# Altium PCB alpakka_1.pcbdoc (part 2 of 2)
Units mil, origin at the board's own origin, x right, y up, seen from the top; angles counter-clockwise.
Board outline 6704.54 x 4318.9 mil, 4 copper layers (Top Layer, Inner1, Inner2, Bottom Layer); 97 components, 87 nets, 400 pads, 319 vias.
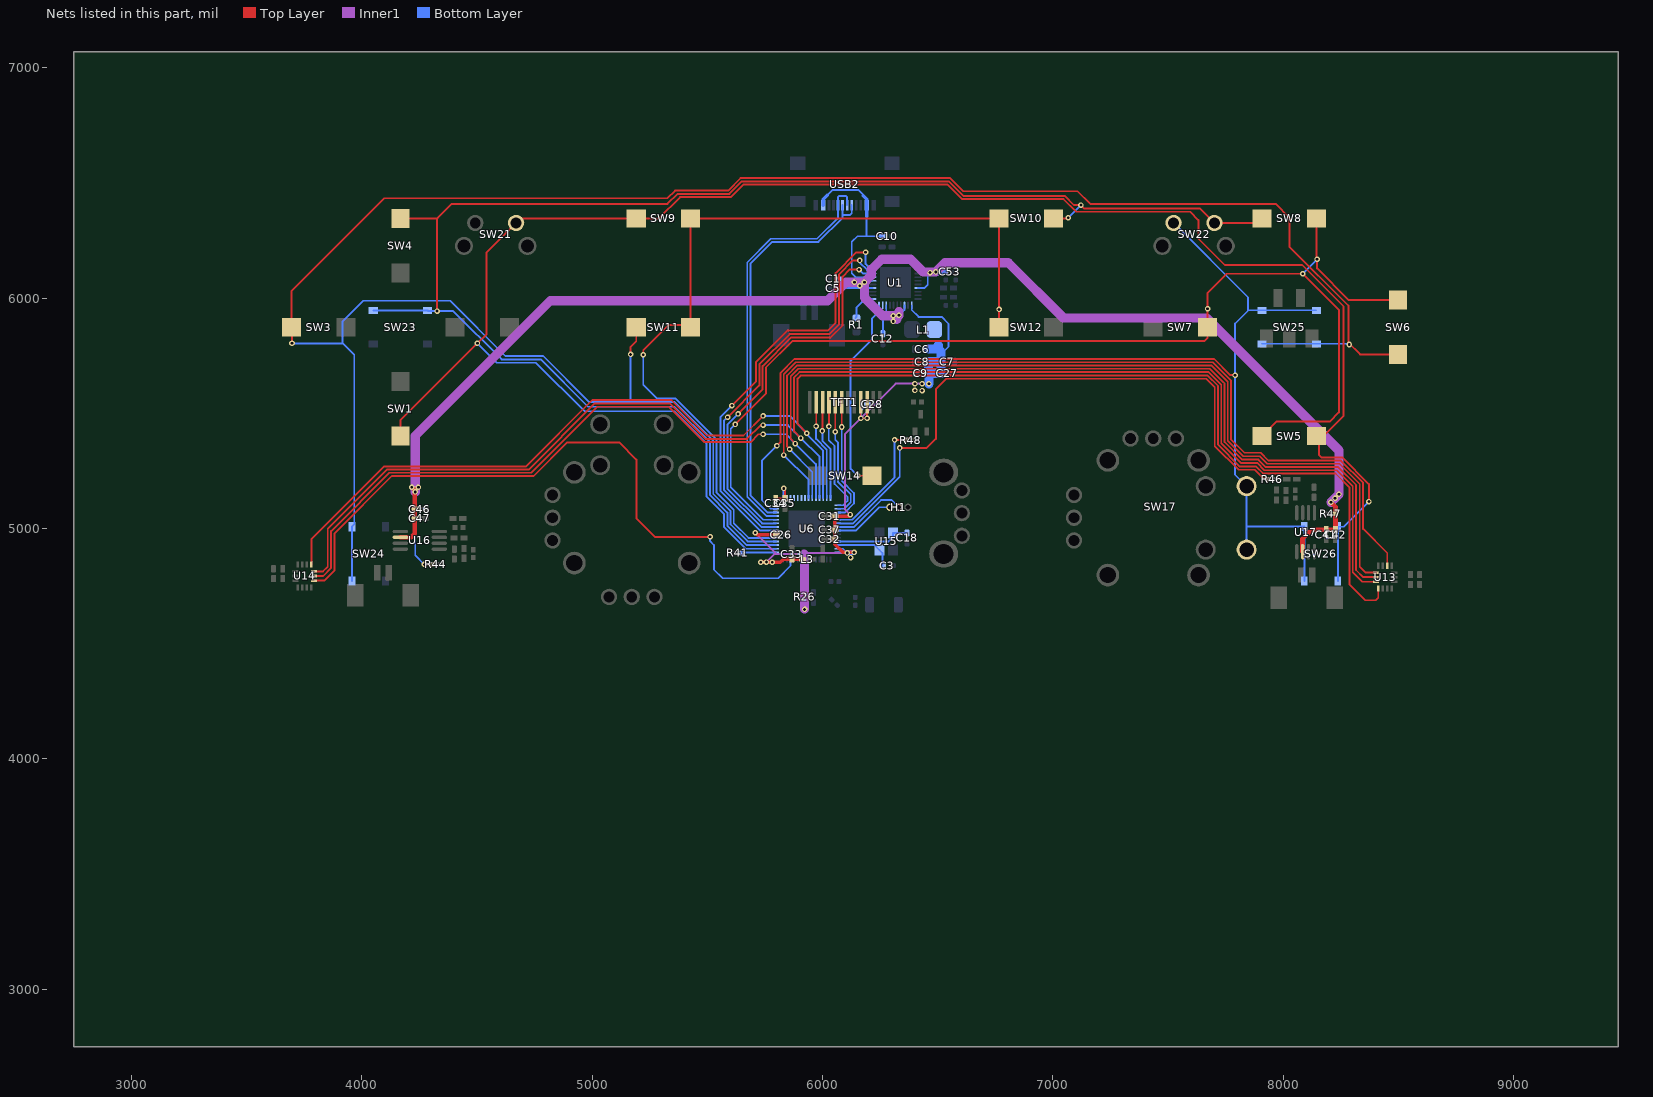
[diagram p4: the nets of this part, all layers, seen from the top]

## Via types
v1: diameter 24.02, hole 12.01, Top Layer to Bottom Layer, 310 vias
v2: diameter 24, hole 12, Top Layer to Bottom Layer, 9 vias

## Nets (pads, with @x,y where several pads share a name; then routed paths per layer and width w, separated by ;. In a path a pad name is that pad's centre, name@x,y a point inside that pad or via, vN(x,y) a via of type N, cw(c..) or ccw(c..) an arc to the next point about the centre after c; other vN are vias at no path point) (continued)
GPIO7: U6.12 U14.12 | length 2927.4
  Top Layer w8: U14.12@3792.13,4773.54 3837.58,4773.54 3882.27,4818.23 3882.27,4978.23 4131.27,5227.23 4746.27,5227.23 4892.27,5373.23 5117.27,5373.23 5192.27,5298.23 5192.27,5043.23 5272.27,4963.23 v1(5512.27,4963.23)
  Bottom Layer w8: v1(5512.27,4963.23) 5512.27,4944.35 5529.28,4927.34 5529.28,4821.22 5567.17,4783.33 5807.37,4783.33 5861.4,4837.36 U6.12@5861.4,4864.07
GPIO10: R41.2 U6.15 | length 149.8
  Bottom Layer w8: R41.2@5649.31,4898.23 5651.66,4895.87 U6.15@5798.11,4895.87
GPIO11: SW1.1 SW5.1 SW9.1 SW21.1 SW26.3 SW26.4 U6.16 | length 8373.5
  Top Layer w8: SW1.1@4168.16,5400.65 4168.16,5469.12 v1(4502.27,5803.23) 4542.27,5843.23 4542.27,6198 SW21.1@4670.12,6325.86 4689.82,6345.56 SW9.1@5191.75,6345.56 5289.6,6345.56 5382.27,6438.23 5602.27,6438.23 5656.27,6492.23 6543.07,6492.23 6606.18,6429.11 7046.39,6429.11 7101.27,6374.23 7596.27,6374.23 7632.27,6338.23 7632.27,6258.23 7747.27,6143.23 8082.27,6143.23 8262.27,5963.23 8262.27,5488.23 SW5.1@8156.27,5382.23 ; SW5.1@8144.47,5400.66 8144.47,5394.03 SW5.1@8156.27,5382.23 ; v1(8372.27,5116.24) 8372.27,5192.22 8256.26,5308.23 8165.28,5308.23 8156.27,5317.23 SW5.1@8156.27,5382.23
  Bottom Layer w8: v1(4502.27,5803.23) 4586.26,5719.24 4756.26,5719.24 4967.27,5508.23 5357.87,5508.23 5496.27,5369.83 5496.27,5139.23 5572.27,5063.23 5572.27,5006.18 5666.83,4911.61 U6.16@5798.11,4911.61 ; SW21.1@4670.12,6325.86 SW21.1@4675.12,6320.86 ; SW26.4@8238.09,4770.95 8238.09,5007.17 8263.2,5007.17 v1(8372.27,5116.24)
GPIO12: SW4.1 SW8.1 SW10.1 SW22.1 SW23.3 SW23.4 U6.17 | length 6789.4
  Top Layer w8: SW4.1@4168.16,6345.47 4328.24,6345.47 ; v1(4327.27,5943.23) 4327.27,6344.5 4328.24,6345.47 ; SW10.1@7002.77,6345.56 7064.6,6345.56 v1(7067.27,6348.23) ; SW8.1@7908.25,6360.91 SW8.1@7908.25,6345.56 7888.55,6325.86 SW22.1@7701.62,6325.86 7639.25,6388.23 7137.27,6388.23 v1(7122.27,6403.23) 7092.07,6403.23 7052.18,6443.11 6611.98,6443.11 6548.87,6506.23 5650.07,6506.23 5596.07,6452.23 5371.27,6452.23 5327.27,6408.23 4391,6408.23 4328.24,6345.47
  Bottom Layer w8: SW23.3@4050.05,5945.89 SW23.4@4286.27,5945.89 4288.93,5943.23 v1(4327.27,5943.23) 4397.27,5943.23 4607.27,5733.23 4777.27,5733.23 4982.27,5528.23 5357.67,5528.23 5512.27,5373.63 5512.27,5143.43 5587.27,5068.43 5587.27,5010.97 5670.88,4927.36 U6.17@5798.11,4927.36 ; v1(7067.27,6348.23) v1(7122.27,6403.23)
GPIO13: SW3.1 SW6.1 SW11.1 SW24.1 SW24.2 SW25.3 SW25.4 U6.18 | length 10327.3
  Top Layer w8: v1(3697.27,5803.23) 3697.27,5871.44 SW3.1@3695.65,5873.06 3695.65,6031.61 4097.27,6433.23 5327.27,6433.23 5360.27,6466.23 5590.27,6466.23 5644.27,6520.23 6554.67,6520.23 6611.67,6463.23 7107.27,6463.23 7162.27,6408.23 7967.27,6408.23 8027.27,6348.23 8027.27,6223.23 8283.75,5966.75 8283.75,5805.06 8333.86,5754.95 SW6.1@8498.86,5754.95 ; v1(5167.27,5755.24) 5167.27,5788.23 5191.75,5812.71 SW11.1@5191.75,5873.06
  Bottom Layer w8: v1(3697.27,5803.23) 3917.27,5803.23 ; SW24.2@3957.53,4770.75 SW24.1@3957.53,5006.97 3967.53,5016.97 3967.53,5752.97 3917.27,5803.23 ; v1(5167.27,5755.24) 5167.27,5549.5 5167.76,5549.01 ; U6.18@5798.11,4943.11 5674.93,4943.11 5601.27,5016.77 5601.27,5074.23 5526.27,5149.23 5526.27,5379.43 5356.68,5549.01 5167.76,5549.01 ; SW25.4@7907.15,5801.23 8143.37,5801.23 8284.27,5801.23 v1(8287.27,5798.23) ; 3917.27,5803.23 3917.27,5898.23 4007.27,5988.23 4383.4,5988.23 4623.4,5748.23 4787.27,5748.23 4986.48,5549.01 5167.76,5549.01
GPIO14: SW9.2 SW10.2 SW11.2 SW12.2 U6.19 | length 3708.5
  Top Layer w8: v1(5222.27,5753.23) 5222.27,5773.23 5332.1,5883.06 5417.97,5883.06 SW11.2@5427.97,5873.06 SW9.2@5427.97,6345.56 SW10.2@6766.55,6345.56 v1(6766.55,5950.4) SW12.2@6766.55,5873.06
  Bottom Layer w8: v1(5222.27,5753.23) 5222.27,5623.23 5282.27,5563.23 5362.27,5563.23 5540.27,5385.23 5540.27,5155.23 5615.27,5080.23 5615.27,5022.57 5678.98,4958.86 U6.19@5798.11,4958.86
GPIO15: U1.40 U6.21 | length 1819.7
  Top Layer w8: v1(5607.27,5533.23) 5712.27,5638.23 5712.27,5723.23 5847.27,5858.23 6022.27,5858.23 6057.27,5893.23 6057.27,6108.23 6147.27,6198.23 v1(6187.27,6198.23)
  Bottom Layer w8: v1(5607.27,5533.23) 5595.72,5521.68 5595.72,5521.25 5557.27,5482.8 5557.27,5163.23 5730.14,4990.35 U6.21@5798.11,4990.35 ; v1(6187.27,6198.23) 6187.27,6148.03 6197.61,6137.69 U1.40@6218.17,6137.69
GPIO16: U1.39 U6.22 | length 1729.8
  Top Layer w8: v1(5588.28,5482.68) 5726.27,5620.67 5726.27,5712.23 5857.27,5843.23 6029.49,5843.23 6072.27,5886.01 6072.27,6103.23 6132.27,6163.23 v1(6162.27,6163.23)
  Bottom Layer w8: v1(5588.28,5482.68) 5572.27,5466.67 5572.27,5168.03 5734.19,5006.1 U6.22@5798.11,5006.1 ; v1(6162.27,6163.23) 6162.27,6153.23 6193.61,6121.89 U1.39@6218.17,6121.89
GPIO17: U1.38 U6.23 | length 1651.2
  Top Layer w8: v1(5633.61,5496.89) 5740.27,5603.55 5740.27,5704.22 5865.28,5829.23 6035.84,5829.23 6087.27,5880.65 6087.27,6093.23 6117.27,6123.23 v1(6159.28,6123.23)
  Bottom Layer w8: v1(5633.61,5496.89) 5587.27,5450.55 5587.27,5172.83 5738.24,5021.85 U6.23@5798.11,5021.85 ; v1(6159.28,6123.23) 6176.32,6106.19 U1.38@6218.17,6106.19
GPIO18: SW5.2 SW6.2 SW7.2 SW8.2 U6.24 | length 5210.5
  Top Layer w8: v1(5621.33,5451.17) 5754.27,5584.1 5754.27,5698.42 5869.08,5813.23 7657.27,5813.23 7672.07,5828.03 SW7.2@7672.07,5873.06 v1(7672.07,5953.23) 7672.07,6023.03 7754.55,6105.51 v1(8084.99,6105.51) 8242.27,5948.23 8242.27,5503.23 8202.27,5463.23 7970.82,5463.23 SW5.2@7908.25,5400.66 ; SW8.2@8144.47,6345.56 8144.47,6171.03 v1(8147.27,6168.23) 8147.27,6128.23 8284.33,5991.17 SW6.2@8498.86,5991.17
  Bottom Layer w8: v1(5621.33,5451.17) 5602.27,5432.1 5602.27,5177.63 5742.29,5037.6 U6.24@5798.11,5037.6 ; v1(8084.99,6105.51) 8147.27,6167.79 v1(8147.27,6168.23)
GPIO19: U6.25 USB2.A7 USB2.B7 | length 1820.4
  Bottom Layer w8: U6.25@5798.11,5053.35 5777.02,5053.35 5776.15,5054.22 5756.27,5054.22 5673.27,5137.23 5673.27,6154.23 5776.37,6257.33 5976.37,6257.33 6067.73,6348.69 USB2.B7@6067.73,6403.19 6067.27,6403.65 6067.27,6438.23 6072.27,6443.23 6102.27,6443.23 6107.1,6438.39 USB2.A7@6107.1,6403.19
GPIO20: U6.26 USB2.A6 USB2.B6 | length 1763.6
  Bottom Layer w8: U6.26@5798.11,5069.09 5777.02,5069.09 5776.15,5068.22 5762.27,5068.22 5687.27,5143.23 5687.27,6148.43 5782.17,6243.33 5982.17,6243.33 6087.42,6348.58 6087.42,6359.84 ; USB2.A6@6087.42,6403.19 6087.42,6359.84 ; USB2.B6@6126.79,6403.19 6127.27,6402.71 6127.27,6368.23 6118.88,6359.84 6087.42,6359.84
GPIO21: SW17.b SW17.d SW22.2 SW25.1 SW25.2 SW26.1 SW26.2 U6.27 | length 5069.6
  Top Layer w8: v1(5802.27,5358.23) 5817.27,5373.23 5817.27,5674.23 5878.26,5735.23 7700.27,5735.23 7770.42,5665.08 v1(7791.01,5665.08)
  Bottom Layer w8: U6.27@5798.11,5084.84 5775.65,5084.84 5737.27,5123.23 5737.27,5293.23 v1(5802.27,5358.23) ; SW22.2@7524.46,6325.86 7847.27,6003.05 7847.27,5945.41 ; SW17.b@7841.01,4907.77 7841.01,5008.23 ; SW26.2@8092.43,4770.95 8092.43,5007.17 8091.37,5008.23 7841.01,5008.23 ; SW25.1@8143.37,5946.89 7848.74,5946.89 7847.27,5945.41 ; 7841.01,5008.23 SW17.d@7841.01,5183.36 7791.01,5233.36 v1(7791.01,5665.08) 7791.01,5889.15 7847.27,5945.41
GPIO33: U6.38 U13.13 U14.13 | length 6450.1
  Top Layer w8: U14.13@3792.13,4793.23 3832.27,4793.23 3867.27,4828.23 3867.27,4988.23 4120.27,5241.23 4735.27,5241.23 5022.27,5528.23 5332.27,5528.23 5486.27,5374.23 5688.27,5374.23 5722.27,5408.23 v1(5742.27,5408.23) ; v1(5882.27,5368.23) 5862.27,5388.23 5862.27,5659.84 5895.66,5693.23 7682.27,5693.23 7740.27,5635.23 7740.27,5635.03 7745.27,5630.03 7745.27,5375.43 7822.47,5298.23 7892.67,5298.23 7924.67,5266.23 8238.87,5266.23 8316.27,5188.83 8316.27,4819.23 8347.27,4788.22 U13.13@8402.41,4788.22
  Bottom Layer w8: v1(5742.27,5408.23) 5842.27,5408.23 v1(5882.27,5368.23) 5971.64,5278.85 U6.38@5971.64,5132.38
GPIO34: U6.39 U13.14 U14.14 | length 6472.4
  Top Layer w8: U14.14@3792.13,4812.91 3831.95,4812.91 3852.27,4833.23 3852.27,4998.23 4109.27,5255.23 4724.27,5255.23 5011.27,5542.23 5338.07,5542.23 5492.07,5388.23 5672.27,5388.23 5732.27,5448.23 v1(5742.27,5448.23) ; v1(5906.05,5392) 5877.27,5420.78 5877.27,5655.04 5900.46,5678.23 7677.27,5678.23 7731.27,5624.23 7731.27,5369.03 7816.07,5284.23 7886.87,5284.23 7918.87,5252.23 8233.07,5252.23 8302.27,5183.03 8302.27,4809.99 8343.71,4768.54 U13.14@8402.41,4768.54
  Bottom Layer w8: v1(5742.27,5448.23) 5849.82,5448.23 v1(5906.05,5392) 5987.39,5310.66 U6.39@5987.39,5132.38
GPIO35: U6.40 U13.1 U14.1 | length 6573.7
  Top Layer w8: U14.1@3781.8,4842.91 3781.8,4952.76 4098.27,5269.23 4713.27,5269.23 5001.27,5557.23 5344.28,5557.23 5498.28,5403.23 5657.27,5403.23 v1(5742.27,5488.23) ; v1(5932.27,5413.23) 5892.27,5453.23 5892.27,5650.24 5905.26,5663.23 7672.07,5663.23 7717.27,5618.03 7717.27,5363.23 7812.27,5268.23 7883.07,5268.23 7913.07,5238.23 8227.27,5238.23 8287.27,5178.23 8287.27,4758.23 8357.27,4688.23 8402.27,4688.23 8412.74,4698.7 U13.1@8412.74,4738.54
  Bottom Layer w8: v1(5742.27,5488.23) 5857.27,5488.23 v1(5932.27,5413.23) 5932.27,5408.43 6003.13,5337.56 U6.40@6003.13,5132.38
GPIO36: TFT1.11 U6.41 | length 434.2
  Top Layer w8: v1(5972.27,5443.23) 5973.25,5444.21 TFT1.11@5973.25,5546.87
  Bottom Layer w8: v1(5972.27,5443.23) 5972.27,5388.23 6018.88,5341.61 U6.41@6018.88,5132.38
GPIO37: TFT1.10 U6.42 | length 429.5
  Top Layer w8: v1(5999.63,5423.23) 6000.81,5424.41 TFT1.10@6000.81,5546.87
  Bottom Layer w8: v1(5999.63,5423.23) 5999.63,5380.66 6034.63,5345.66 U6.42@6034.63,5132.38
GPIO38: TFT1.9 U6.43 | length 512
  Top Layer w8: v1(6028.37,5442.73) TFT1.9@6028.37,5546.87
  Bottom Layer w8: v1(6028.37,5442.73) 6027.27,5441.62 6027.27,5383.23 6052.27,5358.23 6052.27,5193.23 6108.88,5136.62 6108.88,5119.44 6090.04,5100.59 U6.43@6066.42,5100.59
GPIO39: TFT1.8 U6.44 | length 529.3
  Top Layer w8: v1(6055.93,5419.57) TFT1.8@6055.93,5546.87
  Bottom Layer w8: v1(6055.93,5419.57) 6055.93,5384.57 6067.27,5373.23 6067.27,5203.23 6122.88,5147.62 6122.88,5113.64 6094.09,5084.84 U6.44@6066.42,5084.84
GPIO40: TFT1.7 U6.45 | length 547.7
  Top Layer w8: v1(6083.49,5440.05) TFT1.7@6083.49,5546.87
  Bottom Layer w8: U6.45@6066.42,5069.09 6098.13,5069.09 6136.88,5107.84 6136.88,5153.62 6083.49,5207.01 v1(6083.49,5440.05)
GPIO41: R48.1 U6.47 | length 547.9
  Top Layer w8: v1(6313.29,5384.01) 6357.41,5384.01 6365.23,5376.19 R48.1@6365.23,5383.23
  Bottom Layer w8: U6.47@6066.42,5037.6 6129.6,5037.6 6313.29,5221.3 v1(6313.29,5384.01)
GPIO42: R46.1 U6.48 | length 2658
  Top Layer w8: v1(6335.3,5349.08) 6453.12,5349.08 6492.27,5388.23 6492.27,5603.23 6538.27,5649.23 7666.27,5649.23 7703.27,5612.23 7703.27,5357.43 7806.47,5254.23 7877.27,5254.23 7913.27,5218.23 7930.23,5218.23 R46.1@7935.23,5213.23
  Bottom Layer w8: U6.48@6066.42,5021.85 6133.65,5021.85 6335.3,5223.5 v1(6335.3,5349.08)
GPIO43: H1.2 U6.49 | length 327.3
  Bottom Layer w8: U6.49@6066.42,5006.1 6137.7,5006.1 6254.82,5123.23 6300.52,5123.23 H1.2@6332.09,5091.65
GPIO44: H1.1 U6.50 | length 268.3
  Bottom Layer w8: U6.50@6066.42,4990.35 6144.39,4990.35 6245.7,5091.66 H1.1@6292.72,5091.65
GPIO47: U6.37 U13.12 | length 3883.3
  Top Layer w8: v1(5857.27,5343.23) 5846.27,5354.23 5846.27,5663.64 5889.86,5707.23 7688.27,5707.23 7759.27,5636.23 7759.27,5381.23 7827.27,5313.23 7897.47,5313.23 7930.47,5280.23 8244.67,5280.23 8332.27,5192.63 8332.27,4833.23 8357.58,4807.91 U13.12@8402.41,4807.91
  Bottom Layer w8: v1(5857.27,5343.23) 5955.89,5244.6 U6.37@5955.89,5132.38
GPIO48: U6.36 U13.9 | length 3887.5
  Top Layer w8: v1(5832.27,5318.23) 5832.27,5669.43 5884.06,5721.23 7694.27,5721.23 7773.27,5642.23 7773.27,5387.23 7832.27,5328.23 7902.27,5328.23 7936.27,5294.23 8250.47,5294.23 8347.27,5197.42 8347.27,4997.91 8452.11,4893.07 U13.9@8452.11,4837.91
  Bottom Layer w8: v1(5832.27,5318.23) 5940.14,5210.35 U6.36@5940.14,5132.38
PMIC_PWROK: U1.29
PMIC_PWRON: SW14.2 U1.30 | length 866.8
  Top Layer w8: v1(6152.27,5228.23) SW14.2@6215.38,5228.23
  Bottom Layer w8: v1(6152.27,5228.23) 6122.27,5258.23 6122.27,5728.23 6215.67,5821.63 6215.67,5911.63 6245.67,5941.63 U1.30@6245.67,5968.39
SPICLK: U6.33
SPICS0: U6.32
SPID: U6.35
SPIHD: U6.30
SPIQ: U6.34
SPIWP: U6.31
TS: R1.1 U1.31 | length 133.9
  Bottom Layer w8: R1.1@6142.27,5912.89 6147.27,5917.89 6147.27,5958.23 6184.93,5995.89 U1.31@6218.17,5995.89
VBUS: C10.2 U1.37 USB2.A4 USB2.A9 | length 786.6
  Bottom Layer w8: 6020.94,6446.9 6042.27,6468.23 6157.27,6468.23 6179.77,6445.73 ; 6191.75,6354.23 6191.75,6268.74 6192.27,6268.23 ; U1.37@6218.17,6090.39 6145.11,6090.39 6127.27,6108.23 6127.27,6243.23 6152.27,6268.23 6192.27,6268.23 ; C10.2@6260.81,6268.23 6192.27,6268.23
  Bottom Layer w15: USB2.A4@6002.78,6403.18 6002.78,6428.74 6020.94,6446.9 ; 6177.27,6443.23 6191.75,6428.74 USB2.A9@6191.75,6403.18 6191.75,6354.23
VDD3V3: C6.2 C7.2 C8.2 C9.2 C26.2 C27.2 C28.2 C31.2 C32.2 C33.2 C37.2 L1.2 L3.1 R26.2 TFT1.3 TFT1.4 U1.21 U6.20 U6.46 U6.55 U6.56 | length 3298.8
  Top Layer w8: TFT1.4@6166.17,5546.87 6166.17,5479.33 v1(6167.27,5478.23) v1(6193.73,5478.23) TFT1.3@6193.73,5546.87
  Top Layer w15: v1(5708.54,4980.83) 5716.15,4973.23 C26.2@5800.81,4973.23 ; v1(5732.27,4853.23) v1(5782.1,4853.23) 5817.27,4853.23 5830.81,4866.77 C33.2@5867.27,4866.77 5868.34,4865.7 L3.1@5913.21,4865.7 ; v1(6120.48,5059.61) 6114.1,5053.23 C31.2@6053.73,5053.23 C37.2@6053.73,4993.23 C32.2@6053.73,4953.23 6053.73,4931.77 6090.14,4895.36 v1(6137.27,4895.36)
  Inner1 w8: v1(5708.54,4980.83) 5797.27,4892.1 5797.27,4888.23 ; v1(5756.7,4853.8) 5791.14,4888.23 5797.27,4888.23 ; 5919.81,4888.23 5797.27,4888.23 ; 5929.73,4893.23 v1(6107.27,4893.23) ; v1(6120.48,5059.61) 6097.27,5082.83 6097.27,5408.23 v1(6167.27,5478.23) 6317.27,5628.23 v1(6401.24,5628.23) v1(6432.27,5628.23)
  Inner1 w40: 5919.81,4888.23 5922.27,4885.77 v1@5922.27,4650.03
  Bottom Layer w8: v1(5708.54,4980.83) 5714.76,4974.61 U6.20@5798.11,4974.61 ; v1(5922.27,4648.23) R26.2@5922.27,4686.19 ; U6.56@6066.42,4895.87 6104.62,4895.87 6088.88,4911.61 U6.55@6066.42,4911.61 ; U6.46@6066.42,5053.35 6114.23,5053.35 v1(6120.48,5059.61) ; v1(6167.27,5478.23) 6167.27,5509.69 C28.2@6195.81,5538.23 ; U1.21@6387.47,5968.39 6387.47,5948.03 6417.27,5918.23 6517.27,5918.23 6547.27,5888.23 6547.27,5788.23 6514.71,5755.67
  Bottom Layer w20: v1(6107.27,4893.23) 6109.4,4895.36 v1(6137.27,4895.36)
  Bottom Layer w40: 6459.83,5684.33 C8.2@6459.83,5723.23 C7.2@6514.71,5723.23 ; C6.2@6459.83,5778.23 6487.27,5778.23 6502.27,5793.23 6502.27,5778.23 6514.71,5765.79 6514.71,5755.67 C7.2@6514.71,5723.23 ; v1(6462.27,5628.23) 6462.27,5659.69 ; 6482.27,5673.23 C27.2@6520.81,5673.23 ; C27.2@6514.71,5679.33 C7.2@6514.71,5723.23
  other v1: 6122.27,4873.23 6432.27,5598.23 6401.24,5598.76
VDD_SPI: C34.2 C35.2 U6.29 | length 127.4
  Top Layer w8: C34.2@5797.27,5129.69 C35.2@5837.27,5129.69 5837.27,5168.23 v1(5832.27,5173.23)
  Bottom Layer w8: U6.29@5829.91,5132.38 5829.91,5170.87 v1(5832.27,5173.23)
VRTC: C12.2 U1.28 | length 130
  Bottom Layer w8: C12.2@6262.27,5844.69 6262.27,5923.23 6277.27,5938.23 6277.27,5968.29 U1.28@6277.17,5968.39
VSYS: C1.2 C5.2 C41.2 C42.2 C46.2 C47.2 C53.2 R44.1 R47.1 U1.17 U1.23 U1.34 U1.36 U16.6 U17.6 | length 6991.4
  Top Layer w8: v1(4272.27,4843.23) R44.1@4305.23,4843.23 ; R47.1@8224.31,5063.23 R47.1@8227.27,5060.27
  Top Layer w20: U16.6@4167.78,4961.03 4215.07,4961.03 4230.81,4976.77 C47.2@4230.81,5043.23 C46.2@4230.81,5083.23 4230.81,5156.77 v1(4232.27,5158.23) v1@4232.27,5163.23 ; v1(4217.27,5178.23) v1@4232.27,5163.23 ; v1(4246.09,5178.23) 4232.27,5164.41 v1@4232.27,5163.23 ; U17.6@8084.06,4898.74 8084.06,4955.02 8123.73,4994.69 C41.2@8187.27,4994.69 C42.2@8227.27,4994.69 8227.27,5060.27 8227.27,5093.23 v1(8207.27,5113.23)
  Inner1 w40: v1(4232.27,5158.23) 4232.27,5401.46 4819.04,5988.23 6022.27,5988.23 6102.27,6068.23 v1(6182.27,6068.23) ; 6332.27,5941.66 v1(6332.27,5924.63) 6322.27,5914.63 6322.27,5907.92 v1(6306.96,5923.23) 6260.7,5923.23 6182.27,6001.66 v1(6182.27,6068.23) ; v1(8207.27,5113.23) v1(8225.19,5131.15) v1(8242.27,5148.23) 8242.27,5338.23 7667.22,5913.28 7046.17,5913.28 6806.22,6153.23 6532.27,6153.23 v1(6492.27,6113.23) 6437.27,6113.23 6382.27,6168.23 6257.27,6168.23 6212.27,6123.23 6212.27,6098.23 v1(6182.27,6068.23)
  Bottom Layer w8: v1(4232.27,5158.23) 4232.27,4883.23 v1(4272.27,4843.23) ; C5.2@6068.73,6043.23 C5.2@6071.69,6043.19 ; C1.2@6068.73,6083.23 6068.73,6046.15 C5.2@6071.69,6043.19 ; U1.34@6218.17,6043.19 6217.95,6042.96 6142.54,6042.96 6142.31,6043.19 ; U1.36@6218.17,6074.69 6145.29,6074.69 v1(6138.98,6068.38) 6142.31,6065.05 6142.31,6043.19 ; v1(6332.27,5924.63) 6355.97,5948.33 U1.23@6355.97,5968.39 ; U1.17@6414.97,6043.19 6442.23,6043.19 6457.27,6058.23 6457.27,6100.36 v1(6467.27,6110.36) ; C5.2@6071.69,6043.19 6142.31,6043.19
  Bottom Layer w20: v1(6492.27,6113.23) C53.2@6530.81,6113.23
  other v1: 6307.27,5898.23 6162.27,6053.23
XTAL_N: C18.1 U6.53 U15.3 | length 327.2
  Bottom Layer w8: U6.53@6066.42,4943.11 6287.15,4943.11 6306.8,4962.76 U15.3@6306.8,4980.63 6307.74,4979.69 C18.1@6367.27,4979.69
XTAL_P: C3.2 U6.54 U15.1 | length 263.2
  Bottom Layer w8: U6.54@6066.42,4927.36 6226.2,4927.36 U15.1@6247.74,4905.83 6260.81,4892.76 C3.2@6260.81,4838.23
pads on no net: BT1.4 BT1.5 SW15.4 SW15.5 SW21.4 SW22.3 SW22.4 U1.1 U1.4 U1.5 U1.6 U1.7 U1.8 U1.9 U1.10 U1.11 U1.12 U1.13 U1.14 U1.20 U1.24 U1.25 U1.26 U1.27 U1.32 U1.35 U6.28 U8.2 U13.2 U13.3 U13.4 U13.10 U14.2 U14.3 U14.4 U14.10 U18.3 U18.4 USB2.A5 USB2.A8 USB2.B5 USB2.B8

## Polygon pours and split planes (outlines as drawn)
GND on Inner2 (solid, remove dead copper): 3392.27,6733.23 8792.27,6733.23 8792.27,4428.23 3392.27,4428.23
GND on Top Layer (solid, remove dead copper, pour order 8): 3487.27,6728.23 8787.27,6728.23 8787.27,4498.23 3487.27,4498.23
GND on Inner1 (solid, remove dead copper): 3382.27,6728.23 8767.27,6728.23 8767.27,4453.23 3382.27,4453.23
GND on Bottom Layer (solid, remove dead copper, pour order 28): 3382.27,6763.23 8772.27,6763.23 8772.27,4493.23 3382.27,4493.23
VBUS on Bottom Layer (solid, remove dead copper, pour order 10): 5992.27,6413.23 6012.27,6413.23 6012.27,6428.74 6031.75,6448.23 6162.27,6448.23 6182.27,6428.23 6182.27,6379.56 6087.27,6284.56 6087.27,6135.62 6139.66,6083.23 6196.86,6083.23 6204.01,6090.39 6204.01,6098.23 6152.27,6098.23 6142.27,6108.23 6142.27,6208.23 6182.27,6248.23 6266.99,6248.23 6273.36,6254.6 6273.36,6312.13 6202.27,6383.23 6202.27,6455.08 6185.37,6471.98 6023.86,6471.98 6017.6,6478.23 5992.27,6452.89
VDD3V3 on Inner1 (solid, remove dead copper): 5685.09,5331.05 5685.09,4873.6 5730.46,4828.23 5956.83,4828.23 5977.68,4849.07 6123.19,4849.07 6153.21,4879.1 6153.21,5061.22 6222.33,5130.34 6222.33,5340.75 6492.27,5610.68 6492.27,5648.7 6482.74,5658.23 6012.27,5658.23
VDD3V3 on Top Layer (solid, remove dead copper, pour order 0): 6125.26,5083.04 6059.96,5083.04 6040.97,5064.06 6040.97,4909.53 6092.27,4858.23 6132.27,4858.23 6152.27,4878.23 6152.27,5056.03
ALDO2 on Inner1 (solid, remove dead copper): 5152.39,4918.11 5322.27,4748.23 5322.27,4688.23 5292.27,4658.23 5037.27,4658.23 4737.27,4958.23 4737.27,5398.23 5082.27,5743.23 6312.27,5743.23 6462.27,5893.23 6462.27,5978.23 6486.61,6002.57 6486.61,6003.89 6487.76,6002.73 6558.77,6002.73 6843.28,5718.23 6917.27,5718.23 7182.27,5453.23 7345.65,5453.23 7398.66,5400.22 7398.66,5264.62 7232.27,5098.23 7064.99,5098.23 7042.27,5120.95 7042.27,5358.23 6767.27,5633.23 6642.27,5633.23 6612.27,5663.23 5385.18,5663.23 5152.39,5430.44
BAT on Bottom Layer (solid, remove dead copper, pour order 12): 6218.17,6031.39 6150.43,6031.39 6127.27,6008.23 5982.27,6008.23 5952.27,5978.23 5952.27,5908.23 6002.27,5908.23 6042.27,5948.23 6120.61,5948.23 6190.61,6018.23 6202.27,6018.23 6211.43,6027.39 6218.17,6027.39
VDD3V3 on Top Layer (solid, remove dead copper, pour order 2): 5922.27,4845.43 5829.87,4845.43 5809.38,4824.94 5735.56,4824.94 5692.27,4868.23 5692.27,4993.23 5717.27,5018.23 5801.89,5018.23 5822.27,4997.85 5822.27,4903.09 5840.03,4885.33 5911.07,4885.33 5922.27,4874.13
ALDO1 on Inner1 (solid, remove dead copper): 3624.35,4980.31 3582.27,4938.23 3582.27,4828.76 3607.8,4803.23 4122.51,4803.23 5074.23,5754.95 6308.99,5754.95 6452.27,5898.23 6452.27,5978.23 6477.27,6003.23 6587.27,6003.23 6855.27,5735.23 7540.27,5735.23 7692.27,5583.23 7692.27,5422.41 7860.45,5254.23 7860.45,4865.04 8057.27,4668.23 8548.11,4668.23 8578.64,4698.76 8578.64,4732.22 8530.56,4780.3 8145.2,4780.3 8067.27,4858.23 8067.27,5428.23 7657.81,5837.69 6863.56,5837.69 6623.02,6078.23 6472.27,6078.23 6387.47,5993.43 6387.47,5934.13 6316.57,5863.23 4902.27,5863.23 4293.73,5254.69 4293.73,5158.23 4115.81,4980.31
VSYS on Bottom Layer (solid, remove dead copper, pour order 14): 6351.05,5958.31 6335.97,5943.23 6307.28,5943.23 6287.28,5923.23 6287.28,5893.21 6297.27,5883.23 6317.27,5883.23 6360.95,5926.91 6360.95,5958.31
ALDO1 on Top Layer (solid, remove dead copper, pour order 4): 3647.82,4928.23 3622.27,4928.23 3597.27,4903.23 3597.27,4832.98 3617.27,4812.98 3676.9,4812.98 3687.58,4823.66 3687.58,4888.47
VSYS on Inner1 (solid, remove dead copper): 4877.27,5878.23 4281.38,5282.33 4281.38,5178.23 4231.38,5128.23 4172.27,5128.23 4119.69,5180.81 4119.69,5429.35 4763.57,6073.23 5867.27,6073.23 6072.27,6278.23 6837.27,6278.23 7072.27,6043.23 7768.68,6043.23 8307.27,5504.64 8307.27,5058.23 8297.27,5048.23 8188.63,5048.23 8120.1,5116.76 8120.1,5395.4 7662.27,5853.23 6880.04,5853.23 6670.18,6063.09 6437.13,6063.09 6392.27,6018.23 6392.27,5940.83 6329.67,5878.23
$1N24407 on Bottom Layer (solid, remove dead copper, pour order 16): 6371.67,5927.63 6347.05,5903.01 6347.05,5831.37 6357.56,5820.86 6414.9,5820.86 6427.27,5833.23 6427.27,5905.6 6411.53,5905.6 6371.67,5945.46
ALDO1 on Top Layer (solid, remove dead copper, pour order 6): 8496.44,4768.54 8508.01,4756.97 8508.01,4718.22 8523,4703.23 8562.27,4703.23 8602.27,4743.23 8602.27,4762.28 8593.41,4771.14 8519.55,4771.14 8516.95,4768.54
VDD3V3 on Bottom Layer (solid, remove dead copper, pour order 18): 6467.27,5898.23 6467.27,5851.03 6453.6,5837.36 6453.6,5821.33 6445.49,5813.23 6445.49,5694.34 6436.18,5685.03 6436.18,5662.13 6417.27,5643.23 6399.24,5643.23 6384.24,5628.23 6384.24,5591.26 6397.27,5578.23 6477.27,5578.23 6529.81,5630.77 6529.81,5839.91 6471.49,5898.23
VSYS on Bottom Layer (solid, remove dead copper, pour order 20): 6202.67,6081.26 6202.67,6038.23 6137.27,6038.23 6127.27,6028.23 6062.27,6028.23 6061.7,6027.66 6057.27,6032.08 6057.27,6099.28 6066.22,6108.23 6107.27,6108.23 6134.23,6081.26
ALDO1 on Bottom Layer (solid, remove dead copper, pour order 22): 6458.84,6024.8 6534.27,6024.8 6543.17,6033.7 6543.17,6088.23 6492.27,6088.23 6472.27,6068.23 6472.27,6038.23
VSYS on Bottom Layer (solid, remove dead copper, pour order 24): 6527.81,6132.86 6468.2,6132.86 6448.57,6113.23 6448.57,6064.53 6432.27,6048.23 6424.12,6048.23 6424.12,6041.38 6427.27,6038.23 6452.27,6038.23 6467.27,6053.23 6467.27,6083.23 6477.27,6093.23 6517.65,6093.23 6527.81,6103.39
ALDO2 on Bottom Layer (solid, remove dead copper, pour order 26): 6528.37,6016.86 6423.98,6016.86 6422.27,6015.15 6422.27,6008.23 6424.81,6005.69 6454.81,6005.69 6472.27,5988.23 6472.27,5959.67 6503.71,5928.23 6557.27,5928.23 6557.27,5978.23 6527.27,6008.23 6527.27,6015.76

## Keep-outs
Board Outline Layer:
  circle w1: c3774.43,5558.11 r79
  region: 3853.43,5558.11 cw(c3774.43,5558.11) 3695.43,5558.11 cw(c3774.43,5558.11)
  circle w1: c3774.43,5046.3 r40
  region: 3814.43,5046.3 cw(c3774.43,5046.3) 3734.43,5046.3 cw(c3774.43,5046.3)
  circle w1: c4601.21,5558.11 r79
  region: 4680.21,5558.11 cw(c4601.21,5558.11) 4522.21,5558.11 cw(c4601.21,5558.11)
  circle w1: c5506.72,5558.11 r79
  region: 5585.72,5558.11 cw(c5506.72,5558.11) 5427.72,5558.11 cw(c5506.72,5558.11)
  circle w1: c6687.82,5558.11 r79
  region: 6766.82,5558.11 cw(c6687.82,5558.11) 6608.82,5558.11 cw(c6687.82,5558.11)
  circle w1: c7593.33,5558.11 r79
  region: 7672.33,5558.11 cw(c7593.33,5558.11) 7514.33,5558.11 cw(c7593.33,5558.11)
  circle w1: c8420.1,5558.11 r79
  region: 8499.1,5558.11 cw(c8420.1,5558.11) 8341.1,5558.11 cw(c8420.1,5558.11)
  circle w1: c4601.21,5046.3 r40
  region: 4641.21,5046.3 cw(c4601.21,5046.3) 4561.21,5046.3 cw(c4601.21,5046.3)
  circle w1: c4601.21,6069.92 r40
  region: 4641.21,6069.92 cw(c4601.21,6069.92) 4561.21,6069.92 cw(c4601.21,6069.92)
  circle w1: c5506.72,5046.3 r40
  region: 5546.72,5046.3 cw(c5506.72,5046.3) 5466.72,5046.3 cw(c5506.72,5046.3)
  circle w1: c5506.72,6069.92 r40
  region: 5546.72,6069.92 cw(c5506.72,6069.92) 5466.72,6069.92 cw(c5506.72,6069.92)
  circle w1: c6687.82,5046.3 r40
  region: 6727.82,5046.3 cw(c6687.82,5046.3) 6647.82,5046.3 cw(c6687.82,5046.3)
  circle w1: c6687.82,6069.92 r40
  region: 6727.82,6069.92 cw(c6687.82,6069.92) 6647.82,6069.92 cw(c6687.82,6069.92)
  circle w1: c8420.1,5046.3 r40
  region: 8460.1,5046.3 cw(c8420.1,5046.3) 8380.1,5046.3 cw(c8420.1,5046.3)
  circle w1: c7593.33,6069.92 r40
  region: 7633.33,6069.92 cw(c7593.33,6069.92) 7553.33,6069.92 cw(c7593.33,6069.92)
  circle w1: c7593.33,5046.3 r40
  region: 7633.33,5046.3 cw(c7593.33,5046.3) 7553.33,5046.3 cw(c7593.33,5046.3)
  region: 6162.27,4793.23 6642.27,4793.23 6642.27,4618.23 6162.27,4618.23
  region: 6786.25,5302.14 6983.1,5302.27 cw(c6983.1,5262.91) 7022.47,5262.9 7022.47,4829.76 cw(c6982.82,4830.04) 6983.1,4790.39 6786.25,4790.39 cw(c6786.25,4829.76) 6746.88,4829.76 6746.88,5262.9 cw(c6786.25,5262.76)
  lines w1: 6746.88,4829.76 ccw(c6786.25,4829.76) 6786.25,4790.39 6983.1,4790.39 ccw(c6982.82,4830.04) 7022.47,4829.76 7022.47,5262.9 ccw(c6983.1,5262.91) 6983.1,5302.27 6786.25,5302.14 ccw(c6786.25,5262.76) 6746.88,5262.9 6746.88,4829.76
  lines w5.91: 3538.21,4618.23 3538.21,5956.81 4089.39,6507.99 5546.09,6507.99 5669.2,6631.1 6525.34,6631.1 6648.45,6507.99 8105.14,6507.99 8656.32,5956.81 8656.32,4618.23 3538.21,4618.23

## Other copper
Top Layer:
  drawing of 305 lines, arcs and shapes, not listed
Inner1:
  region net ALDO2: 4808.41,5192.98 4848.41,5192.98 4848.63,5186.36 4848.98,5183.04 4849.55,5179.77 4850.38,5176.6 4851.54,5173.58 4853.06,5170.75 4854.99,5168.18 4801.84,5168.18 4803.77,5170.75 4805.28,5173.58 4806.44,5176.6 4807.28,5179.77 4807.84,5183.04 4808.19,5186.36
  region net ALDO2: 4876.66,5124.77 4848.38,5096.49 4843.54,5101.01 4840.95,5103.12 4838.23,5105.03 4835.4,5106.68 4832.45,5108 4829.38,5108.92 4826.19,5109.38 4863.77,5146.96 4864.23,5143.77 4865.16,5140.7 4866.47,5137.75 4868.12,5134.92 4870.03,5132.2 4872.14,5129.61
  region net ALDO2: 5222.28,4722.58 5250.56,4750.86 5255.4,4746.34 5258,4744.23 5260.71,4742.32 5263.54,4740.67 5266.49,4739.35 5269.56,4738.43 5272.75,4737.97 5235.17,4700.39 5234.71,4703.58 5233.79,4706.65 5232.47,4709.6 5230.82,4712.43 5228.91,4715.15 5226.8,4717.74
  region net ALDO2: 7357.4,5341.77 7317.4,5341.77 7317.18,5348.39 7316.83,5351.71 7316.26,5354.98 7315.42,5358.15 7314.27,5361.17 7312.75,5363.99 7310.82,5366.57 7363.97,5366.57 7362.04,5363.99 7360.52,5361.17 7359.37,5358.15 7358.53,5354.98 7357.96,5351.71 7357.62,5348.39
  region net ALDO2: 7072.12,5192.98 7112.12,5192.98 7112.34,5186.36 7112.68,5183.03 7113.25,5179.76 7114.09,5176.59 7115.24,5173.57 7116.76,5170.75 7118.69,5168.17 7065.54,5168.17 7067.47,5170.75 7068.99,5173.57 7070.14,5176.59 7070.98,5179.76 7071.55,5183.03 7071.9,5186.36
  region net ALDO2: 7140.36,5164.74 7140.36,5124.74 7133.74,5124.51 7130.41,5124.17 7127.14,5123.6 7123.97,5122.76 7120.95,5121.61 7118.13,5120.09 7115.55,5118.16 7115.55,5171.31 7118.13,5169.38 7120.95,5167.86 7123.97,5166.71 7127.14,5165.87 7130.41,5165.3 7133.74,5164.96
  region net VDD3V3: 6106.1,5068.34 6111.75,5074 6112.77,5073.14 6113.83,5072.53 6114.93,5072.13 6116.08,5071.88 6118.54,5071.7 6121.24,5071.6 6108.5,5058.86 6108.4,5061.56 6108.21,5064.01 6107.97,5065.16 6107.57,5066.26 6106.96,5067.32
  region net VDD3V3: 5722.93,4972.1 5717.27,4966.45 5716.25,4967.31 5715.19,4967.92 5714.09,4968.32 5712.94,4968.56 5710.49,4968.75 5707.79,4968.85 5720.52,4981.59 5720.62,4978.89 5720.81,4976.43 5721.05,4975.28 5721.46,4974.18 5722.07,4973.12
  region net VDD3V3: 6090.92,4889.23 6090.92,4897.23 6092.25,4897.34 6093.43,4897.66 6094.5,4898.15 6095.48,4898.79 6097.35,4900.4 6099.33,4902.23 6099.33,4884.22 6097.35,4886.06 6095.48,4887.66 6094.5,4888.3 6093.43,4888.8 6092.25,4889.12
  region net VDD3V3: 6158.54,5463.84 6152.88,5469.5 6153.74,5470.52 6154.35,5471.58 6154.75,5472.68 6155,5473.83 6155.19,5476.28 6155.28,5478.98 6168.02,5466.24 6165.32,5466.15 6162.87,5465.96 6161.72,5465.71 6160.62,5465.31 6159.56,5464.7
  region net VDD3V3: 6176,5492.62 6181.66,5486.96 6180.8,5485.94 6180.19,5484.88 6179.78,5483.78 6179.54,5482.63 6179.35,5480.18 6179.25,5477.48 6166.52,5490.21 6169.22,5490.31 6171.67,5490.5 6172.82,5490.74 6173.92,5491.15 6174.98,5491.76
  region net VDD3V3: 6415.92,5624.23 6415.92,5632.23 6417.25,5632.34 6418.43,5632.66 6419.5,5633.15 6420.48,5633.79 6422.35,5635.4 6424.33,5637.23 6424.33,5619.22 6422.35,5621.06 6420.48,5622.66 6419.5,5623.3 6418.43,5623.8 6417.25,5624.12
  region net VDD3V3: 5765.43,4868.18 5771.09,4862.53 5770.23,4861.51 5769.62,4860.45 5769.22,4859.35 5768.97,4858.2 5768.79,4855.74 5768.69,4853.04 5755.95,4865.78 5758.65,4865.88 5761.1,4866.07 5762.25,4866.31 5763.35,4866.71 5764.41,4867.32
  region net VDD3V3: 6417.59,5632.23 6417.59,5624.23 6416.26,5624.12 6415.08,5623.8 6414.01,5623.3 6413.03,5622.66 6411.16,5621.06 6409.18,5619.22 6409.18,5637.23 6411.16,5635.4 6413.03,5633.79 6414.01,5633.15 6415.08,5632.66 6416.26,5632.34
  region net VDD3V3: 6384.89,5624.23 6384.89,5632.23 6386.22,5632.34 6387.4,5632.66 6388.46,5633.15 6389.45,5633.79 6391.32,5635.4 6393.3,5637.23 6393.3,5619.22 6391.32,5621.06 6389.45,5622.66 6388.46,5623.3 6387.4,5623.8 6386.22,5624.12
  region net ALDO2: 6607.11,5806.55 cw(c6828.12,6027.57) 6522.26,5963.23 6482.26,5963.23 cw(c6173.63,6033.23) 6397.4,5809.45 6415.96,5771.43 cw(c6500.81,5686.58) 6585.66,5771.43
  region net VDD3V3: 5862.27,4884.23 5869.11,4892.23 ccw(c5869.11,4989.57) 5909.11,4900.83 5902.27,4874.23 ccw(c5862.27,4799.23)
  region net VSYS: 6202.27,6001.66 cw(c6355.05,6001.66) 6226.41,6084.09 6198.13,6112.37 cw(c6102.27,6290.6) 6102.27,6088.23 6102.27,6048.23 cw(c6102.27,5986.29) 6162.27,6001.66
Inner2:
  region net GND: 6634.44,5199.39 6640.1,5193.73 6639.11,5192.48 6638.41,5191 6637.94,5189.32 6637.69,5187.47 6637.63,5185.47 6637.72,5183.36 6638.25,5178.92 6639.83,5169.9 6640.41,5165.79 6640.54,5163.93 6640.52,5162.24 6602.94,5199.82 6604.63,5199.84 6606.49,5199.71 6610.61,5199.13 6619.62,5197.54 6624.07,5197.02 6626.18,5196.92 6628.17,5196.99 6630.02,5197.24 6631.7,5197.7 6633.19,5198.41
  region net GND: 5109.04,4662.91 5095.88,4664.75 5094.48,4665.92 5092.92,4666.81 5091.21,4667.46 5089.37,4667.9 5087.42,4668.17 5085.38,4668.29 5081.12,4668.23 5072.39,4667.73 5068.25,4667.79 5066.29,4668.01 5064.45,4668.4 5108.78,4697.73 5107.74,4692.32 5106.4,4687.41 5105.08,4682.9 5104.05,4678.69 5103.75,4676.67 5103.64,4674.69 5103.75,4672.73 5104.13,4670.79 5104.81,4668.85 5105.83,4666.89 5107.23,4664.92
  region net GND: 3808.62,4707.23 3808.62,4699.23 3807.29,4699.12 3806.11,4698.8 3805.04,4698.3 3804.06,4697.66 3802.19,4696.06 3800.21,4694.22 3800.21,4712.23 3802.19,4710.4 3804.06,4708.79 3805.04,4708.15 3806.11,4707.66 3807.29,4707.34
  region net GND: 6360.5,6124.35 6366.16,6118.69 6365.3,6117.67 6364.69,6116.61 6364.28,6115.51 6364.04,6114.36 6363.85,6111.91 6363.75,6109.21 6351.02,6121.94 6353.72,6122.04 6356.17,6122.23 6357.32,6122.47 6358.42,6122.88 6359.48,6123.49
  region net GND: 6281.27,6012.15 6273.27,6007.22 6273.14,6008.49 6272.77,6009.72 6272.2,6010.9 6271.46,6012.02 6269.61,6014.01 6267.49,6015.63 6284.82,6020.56 6283.52,6018.25 6282.38,6016.5 6281.92,6015.64 6281.57,6014.68 6281.35,6013.54
  region net GND: 6177.88,5862.3 6183.54,5867.96 6184.56,5867.1 6185.62,5866.49 6186.72,5866.08 6187.87,5865.84 6190.32,5865.65 6193.02,5865.55 6180.28,5852.82 6180.19,5855.52 6180,5857.97 6179.75,5859.12 6179.35,5860.22 6178.74,5861.28
  region net GND: 6208.62,5857.57 6208.62,5849.57 6207.29,5849.46 6206.11,5849.14 6205.04,5848.64 6204.06,5848 6202.19,5846.4 6200.21,5844.56 6200.21,5862.57 6202.19,5860.74 6204.06,5859.13 6205.04,5858.49 6206.11,5858 6207.29,5857.68
  region net GND: 5968.62,6047.23 5968.62,6039.23 5967.29,6039.12 5966.11,6038.8 5965.04,6038.3 5964.06,6037.66 5962.19,6036.06 5960.21,6034.22 5960.21,6052.23 5962.19,6050.4 5964.06,6048.79 5965.04,6048.15 5966.11,6047.66 5967.29,6047.34
  region net GND: 6507.38,6209.23 6507.38,6217.23 6508.71,6217.34 6509.89,6217.66 6510.96,6218.15 6511.94,6218.79 6513.81,6220.4 6515.79,6222.23 6515.79,6204.22 6513.81,6206.06 6511.94,6207.66 6510.96,6208.3 6509.89,6208.8 6508.71,6209.12
  region net GND: 5971,4662.62 5976.66,4656.96 5975.8,4655.94 5975.19,4654.88 5974.78,4653.78 5974.54,4652.63 5974.35,4650.18 5974.25,4647.48 5961.52,4660.21 5964.22,4660.31 5966.67,4660.5 5967.82,4660.74 5968.92,4661.15 5969.98,4661.76
  region net GND: 6078.27,4829.58 6086.27,4829.58 6086.38,4828.25 6086.7,4827.07 6087.19,4826 6087.83,4825.02 6089.44,4823.15 6091.27,4821.17 6073.26,4821.17 6075.1,4823.15 6076.7,4825.02 6077.35,4826 6077.84,4827.07 6078.16,4828.25
  region net GND: 6086.27,4796.88 6078.27,4796.88 6078.16,4798.21 6077.84,4799.39 6077.35,4800.45 6076.7,4801.44 6075.1,4803.31 6073.26,4805.29 6091.27,4805.29 6089.44,4803.31 6087.83,4801.44 6087.19,4800.45 6086.7,4799.39 6086.38,4798.21
  region net GND: 6239.41,5449.71 6237.5,5459.12 6238.44,5460.16 6239.09,5461.12 6239.82,5462.94 6240.28,5464.95 6241.04,5467.48 6249.46,5451.55 6246.83,5451.94 6244.1,5451.83 6242.78,5451.56 6241.53,5451.13 6240.4,5450.52
  region net GND: 6248.27,5479.58 6256.27,5479.58 6256.38,5478.25 6256.7,5477.07 6257.19,5476 6257.83,5475.02 6259.44,5473.15 6261.27,5471.17 6243.26,5471.17 6245.1,5473.15 6246.7,5475.02 6247.35,5476 6247.84,5477.07 6248.16,5478.25
  region net GND: 6268.62,5467.23 6268.62,5459.23 6267.29,5459.12 6266.11,5458.8 6265.04,5458.3 6264.06,5457.66 6262.19,5456.06 6260.21,5454.22 6260.21,5472.23 6262.19,5470.4 6264.06,5468.79 6265.04,5468.15 6266.11,5467.66 6267.29,5467.34
  region net GND: 6434.28,5459.23 6437.88,5467.23 6439.26,5467.32 6440.4,5467.57 6441.39,5467.97 6442.29,5468.48 6444.07,5469.77 6446.29,5471.24 6442.69,5453.59 6440.97,5455.66 6439.01,5457.47 6437.93,5458.19 6436.78,5458.74 6435.57,5459.1
  region net GND: 6468.62,5464.83 6468.62,5456.83 6467.29,5456.71 6466.11,5456.4 6465.04,5455.9 6464.06,5455.26 6462.19,5453.66 6460.21,5451.82 6460.21,5469.83 6462.19,5467.99 6464.06,5466.39 6465.04,5465.75 6466.11,5465.26 6467.29,5464.94
  region net GND: 4045.39,4699.23 4037.89,4707.23 4039.12,4707.36 4040.38,4707.73 4041.62,4708.31 4042.81,4709.07 4043.91,4709.96 4044.89,4710.95 4045.69,4712.01 4046.3,4713.11 4053.8,4696.73 4051.35,4697.65 4049.66,4698.45 4047.95,4699.01
  region net GND: 5980.36,5051.98 5986.01,5046.33 5985.15,5045.31 5984.54,5044.25 5984.14,5043.15 5983.9,5042 5983.71,5039.55 5983.61,5036.85 5970.88,5049.58 5973.58,5049.68 5976.03,5049.87 5977.18,5050.11 5978.28,5050.51 5979.34,5051.12
  region net GND: 5986.01,4950.15 5980.36,4944.49 5979.34,4945.35 5978.28,4945.96 5977.18,4946.37 5976.03,4946.61 5973.58,4946.8 5970.88,4946.9 5983.61,4959.63 5983.71,4956.93 5983.9,4954.48 5984.14,4953.33 5984.54,4952.23 5985.15,4951.17
  region net GND: 5896.89,4942.53 5888.89,4942.53 5888.78,4943.86 5888.46,4945.03 5887.97,4946.1 5887.33,4947.08 5885.73,4948.95 5883.89,4950.93 5901.89,4950.93 5900.06,4948.95 5898.46,4947.08 5897.82,4946.1 5897.32,4945.03 5897.01,4943.86
  region net GND: 5984.63,4664.94 5988.04,4679.65 5991.14,4682.51 5994.38,4685.2 5994.15,4667.31 5992.99,4668.12 5991.8,4668.52 5990.57,4668.54 5989.35,4668.25 5988.12,4667.69 5986.92,4666.92
  region net GND: 5998.77,4690.39 6013.49,4693.79 6011.51,4691.51 6010.73,4690.3 6010.18,4689.08 6009.88,4687.85 6009.91,4686.63 6010.3,4685.43 6011.11,4684.28 5993.22,4684.05 5995.92,4687.29
  region net GND: 6249.27,5857.57 ccw(c6249.27,5897.57) 6273.27,5865.57 6277.27,5853.57
Bottom Layer:
  drawing of 257 lines, arcs and shapes, not listed

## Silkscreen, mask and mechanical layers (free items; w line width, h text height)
Bottom Silkscreen Layer:
  lines w6.3: 6008.69,6552.2 6185.85,6552.2 ; 5959.47,6522.68 6235.06,6522.68 ccw(c6235.06,6552.2) 6235.06,6581.73 5959.47,6581.73 ccw(c5959.47,6552.2) 5959.47,6522.68
Mechanical Layer:
  circle w7.87: c7147.47,5374.06 r42.33
  circle w7.87: c7147.47,4719.06 r42.33
  circle w1: c3774.43,5558.11 r79
  circle w1: c3774.43,5046.3 r40
  circle w1: c4601.21,5558.11 r79
  circle w1: c5506.72,5558.11 r79
  circle w1: c6687.82,5558.11 r79
  circle w1: c7593.33,5558.11 r79
  circle w1: c8420.1,5558.11 r79
  circle w1: c4601.21,5046.3 r40
  circle w1: c4601.21,6069.92 r40
  circle w1: c5506.72,5046.3 r40
  circle w1: c5506.72,6069.92 r40
  circle w1: c6687.82,5046.3 r40
  circle w1: c6687.82,6069.92 r40
  circle w1: c8420.1,5046.3 r40
  circle w1: c7593.33,6069.92 r40
  circle w1: c7593.33,5046.3 r40
  lines w1: 6746.88,4829.76 ccw(c6786.25,4829.76) 6786.25,4790.39 6983.1,4790.39 ccw(c6982.82,4830.04) 7022.47,4829.76 7022.47,5262.9 ccw(c6983.1,5262.91) 6983.1,5302.27 6786.25,5302.14 ccw(c6786.25,5262.76) 6746.88,5262.9 6746.88,4829.76
  lines w3.94: 6746.88,4625.04 6746.88,5467.56 7022.47,5467.56 7022.47,4625.04 6746.88,4625.04
  lines w5.91: 3735.06,4618.23 3735.06,5484.37 ; 3735.06,5641.85 3735.06,6153.66 ; 3813.8,4618.23 3813.8,5484.37 ; 3813.8,5641.85 3813.8,6232.4 ; 4561.84,4618.23 4561.84,5484.37 ; 4561.84,5641.85 4561.84,6507.99 ; 4640.58,4618.23 4640.58,5484.37 ; 4640.58,5641.85 4640.58,6507.99 ; 5467.35,4618.23 5467.35,5484.37 ; 5467.35,5641.85 5467.35,6507.99 ; 5546.09,4618.23 5546.09,5484.37 ; 5546.09,5641.85 5546.09,6507.99 ; 6648.45,4613.23 6648.45,5479.37 ; 6648.45,4618.23 6648.45,5484.37 ; 6648.45,5641.85 6648.45,6507.99 ; 6727.19,4613.23 6727.19,5479.37 ; 6727.19,4618.23 6727.19,5484.37 ; 6727.19,5641.85 6727.19,6507.99 ; 7553.96,4613.23 7553.96,5479.37 ; 7553.96,4618.23 7553.96,5484.37 ; 7553.96,5636.85 7553.96,6502.99 ; 7553.96,5641.85 7553.96,6507.99 ; 7632.7,4613.23 7632.7,5479.37 ; 7632.7,4618.23 7632.7,5484.37 ; 7632.7,5636.85 7632.7,6502.99 ; 7632.7,5641.85 7632.7,6507.99 ; 8380.73,4613.23 8380.73,5479.37 ; 8380.73,4618.23 8380.73,5484.37 ; 8380.73,5636.85 8380.73,6227.4 ; 8380.73,5641.85 8380.73,6232.4 ; 8459.47,4613.23 8459.47,5479.37 ; 8459.47,4618.23 8459.47,5484.37 ; 8459.47,5636.85 8459.47,6148.66 ; 8459.47,5641.85 8459.47,6153.66
Mech2:
  drawing of 3479 lines, arcs and shapes, not listed
Mech6:
  circle w5.91: c7553.96,5873.06 r196.85
  circle w5.91: c8498.84,5873.06 r196.85
  circle w5.91: c8026.4,5401.06 r196.85
  circle w5.91: c8026.4,6345.06 r236.22
  circle w5.91: c7553.96,5873.06 r236.22
  circle w5.91: c8026.4,5401.06 r236.22
  circle w5.91: c8498.84,5873.06 r236.22
  circle w3.94: c7475.22,5046.06 r5.57
  circle w3.94: c7435.85,5046.06 r5.57
  circle w5.91: c8026.4,6345.06 r196.85
  lines w3.94: 7420.1,5046.3 7451.6,5046.3 ; 7435.85,5030.55 7435.85,5062.05 ; 7459.47,5046.3 7490.97,5046.3 ; 7475.22,5030.55 7475.22,5062.05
